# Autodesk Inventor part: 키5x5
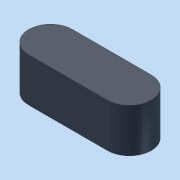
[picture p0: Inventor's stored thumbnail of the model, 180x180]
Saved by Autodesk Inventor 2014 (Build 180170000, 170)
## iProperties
Company: 한국ATC센터
Created: 2014-12
Part Number: 키5x5
Document SubType Name: Modeling
Designer: KYOUNG IL JANG
Density: 1 g/cm^3
Mass: 0.323175 g
Surface Area: 2.9781 cm^2
Volume: 0.323175 cm^3
Material: 일반
Appearance: 진회색
Author: KYOUNG IL JANG
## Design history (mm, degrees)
sketch "스케치1"
  geometry: L1 (-4.5, -2.5)-(4.5, -2.5) reference; L2 (4.5, 2.5)-(-4.5, 2.5) reference; A1 r 2.5 centre (-4.5, 0) between (-4.5, 2.5) and (-4.5, -2.5) reference; A2 r 2.5 centre (4.5, 0) between (4.5, -2.5) and (4.5, 2.5) reference; 1 further point
extrude "돌출1" new body sketch "스케치1" distance "d0" = 5; taper "d1" = 0 deg
node "솔리드1"
node "참조1"
